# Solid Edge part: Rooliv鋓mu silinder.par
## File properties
Author: KULL
Template: Iso Metric Part.par
Last saved by: KULL
Revision: 10
Application: Solid Edge
Accuracy: 0,990
Face Style: Model Default
Fill Style: Normal
Coef. of Thermal Exp: 0.0
Thermal Conductivity: 0.0
Specific Heat: 0.0
Modulus of Elasticity: 0.0
Poisson's Ratio: 0.0
Yield Stress: 0.0
Ultimate Stress: 0.0
Elongation: 0.0
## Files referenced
..\..\Rover_ASM.asm
D:\Solid edge leong\Solid edge Sync practice\ROVER_Heiko_Kull_EKSAM\Roolimise_jupid\frontsteering_1.par
QD:\Solid edge leong\Solid edge Sync practice\ROVER_Heiko_Kull_EKSAM\Rover_ASM.asm
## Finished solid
Body 1: solid body, 72 faces, 146 edges, 74 vertices.
  Faces by surface: cylinder 30, torus 22, plane 12, blend 8
  Edges by curve: circle 94, line 34, intersection 18
Body 2: sheet body, 1 face, 1 edge, 0 vertices.
  Faces by surface: sphere 1
  Edges by curve: circle 1
Bounding box of the edges (mm; curved faces can reach further): 11.000 x 147.387 x 20.004, from (-26, -40, 10.2703) to (-15, 107.3874, 30.2744).
Cylindrical faces by radius (mm): R0.2 x4, R1 x4, R1.1 x4, R1.9548 x2, R2 x1, R2.962 x2, R3 x2, R3.9 x2, R4 x1, R17.9 x2, R18.9 x2, R21.1 x2, R22.1 x2
Toroidal faces (ring radius, tube radius in mm): R1.7 r0.6 x4, R1.7548 r0.2 x2, R2.7 r0.3 x2, R2.762 r0.2 x2, R3.7 r0.3 x2, R4.1 r0.2 x2, R18.1 r0.2 x2, R18.3 r0.6 x2, R21.7 r0.6 x2, R21.9 r0.2 x2
Spherical faces by radius (mm): R3 x1
Planar faces by outward normal: +x 2, +y 2, -x 2, -y 2, oblique 4
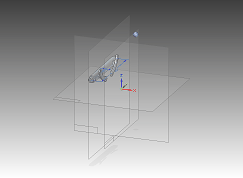
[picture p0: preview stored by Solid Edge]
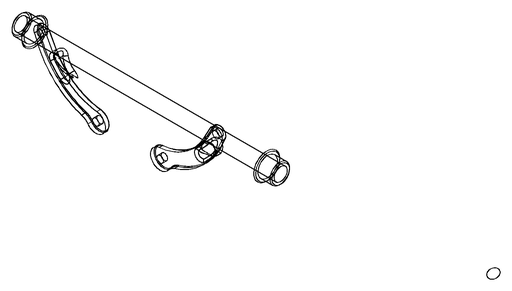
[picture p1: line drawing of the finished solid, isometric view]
